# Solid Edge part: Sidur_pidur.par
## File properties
Author: Türk
Template: Iso Part.par
Last saved by: Türk
Revision: 4
Application: Solid Edge
Accuracy: 0,990
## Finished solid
Body 1: solid body, 23 faces, 55 edges, 34 vertices.
  Faces by surface: plane 17, cylinder 6
  Edges by curve: line 33, circle 14, ellipse 8
Bounding box of the edges (mm): 45.000 x 50.000 x 192.587, from (-22.5, -25, -22.5) to (22.5, 25, 170.0869).
Cylindrical faces by radius (mm): R10 x5, R22.5 x1
Planar faces by outward normal: +x 1, +y 3, +z 1, -x 1, -y 3, oblique 8
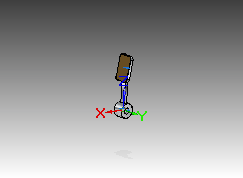
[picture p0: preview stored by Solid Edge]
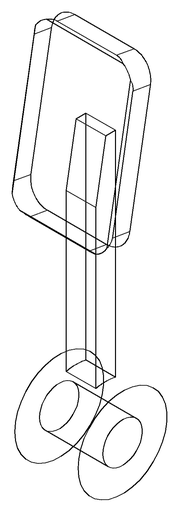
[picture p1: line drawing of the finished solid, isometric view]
